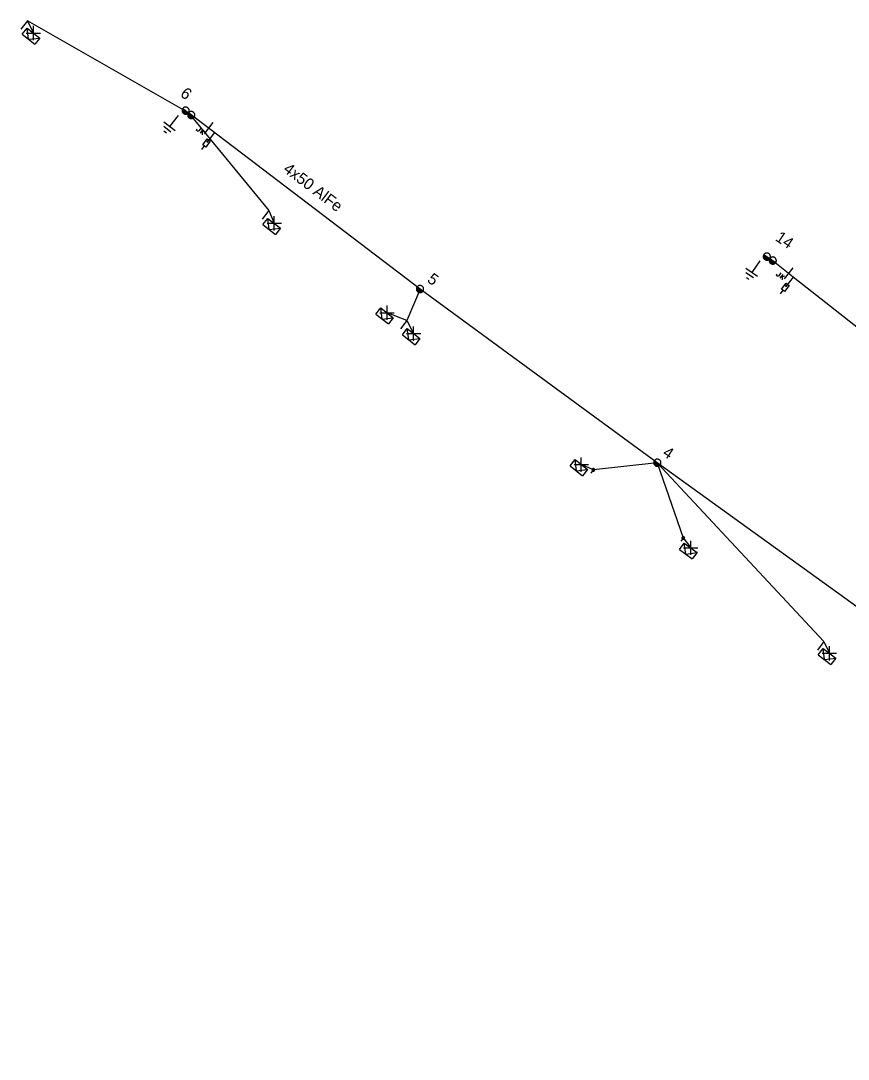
# Model space of a CAD drawing. Extents: x -544780 to -541582, y -1198995 to -1196551.
# Drawn here: x -543128.8 to -543056.3, y -1198154.6 to -1198063.6 of the extents above; entities that cross this region are included whole.
import ezdxf

# ---------------------------------------------------------------- set-up
doc = ezdxf.new("R2010")
doc.units = 0
for name, color, linetype in [('Vrstva 1', 7, 'Continuous'), ('Vrstva 13', 7, 'Continuous'), ('Vrstva 14', 7, 'Continuous'), ('Vrstva 15', 7, 'Continuous'), ('Vrstva 16', 7, 'Continuous'), ('Vrstva 18', 7, 'Continuous'), ('Vrstva 2', 7, 'Continuous'), ('Vrstva 31', 7, 'Continuous'), ('Vrstva 34', 7, 'Continuous'), ('Vrstva 54', 7, 'Continuous'), ('Vrstva 59', 7, 'Continuous'), ('Vrstva 8', 7, 'Continuous'), ('Vrstva 9', 7, 'Continuous')]:
    doc.layers.add(name, color=color, linetype=linetype)

# ---------------------------------------------------------------- blocks, each defined once
blk = doc.blocks.new('NN440')
at = {"layer": 'Vrstva 2'}
for points in [[(0.63, 0), (0.63, 0.06), (0.62, 0.13), (0.6, 0.19), (0.58, 0.25), (0.55, 0.31), (0.51, 0.37), (0.47, 0.42), (0.42, 0.46), (0.37, 0.51), (0.32, 0.54), (0.26, 0.57), (0.2, 0.59), (0.13, 0.61), (0.07, 0.62), (0, 0.63), (-0.06, 0.62), (-0.13, 0.61), (-0.19, 0.59), (-0.26, 0.57), (-0.31, 0.54), (-0.37, 0.51), (-0.42, 0.46), (-0.47, 0.42), (-0.51, 0.37), (-0.54, 0.31), (-0.57, 0.25), (-0.6, 0.19), (-0.62, 0.13), (-0.63, 0.06), (-0.63, 0), (-0.63, -0.07), (-0.62, -0.14), (-0.6, -0.2), (-0.57, -0.26), (-0.54, -0.32), (-0.51, -0.37), (-0.47, -0.43), (-0.42, -0.47), (-0.37, -0.51), (-0.31, -0.55), (-0.26, -0.58), (-0.19, -0.6), (-0.13, -0.62), (-0.06, -0.63), (0, -0.63), (0.07, -0.63), (0.13, -0.62), (0.2, -0.6), (0.26, -0.58), (0.32, -0.55), (0.37, -0.51), (0.42, -0.47), (0.47, -0.43), (0.51, -0.37), (0.55, -0.32), (0.58, -0.26), (0.6, -0.2), (0.62, -0.14), (0.63, -0.07), (0.63, 0)], [(-0.63, 0), (0.63, 0)], [(-0.6, -0.18), (0.57, -0.18)], [(-0.51, -0.32), (0.5, -0.32)], [(-0.37, -0.47), (0.35, -0.47)]]:
    blk.add_lwpolyline(points, dxfattribs=at)
blk = doc.blocks.new('NN450')
at = {"layer": 'Vrstva 2'}
for points in [[(0, 0), (0, 0.07), (-0.01, 0.13), (-0.03, 0.19), (-0.05, 0.25), (-0.08, 0.31), (-0.12, 0.37), (-0.16, 0.42), (-0.21, 0.46), (-0.26, 0.51), (-0.31, 0.54), (-0.37, 0.57), (-0.43, 0.59), (-0.5, 0.61), (-0.56, 0.62), (-0.63, 0.62), (-0.69, 0.62), (-0.75, 0.61), (-0.82, 0.59), (-0.88, 0.57), (-0.94, 0.54), (-0.99, 0.51), (-1.04, 0.46), (-1.09, 0.42), (-1.13, 0.37), (-1.17, 0.31), (-1.2, 0.25), (-1.22, 0.19), (-1.24, 0.13), (-1.25, 0.07), (-1.25, 0), (-1.25, -0.07), (-1.24, -0.13), (-1.22, -0.19), (-1.2, -0.25), (-1.17, -0.31), (-1.13, -0.37), (-1.09, -0.42), (-1.04, -0.46), (-0.99, -0.51), (-0.94, -0.54), (-0.88, -0.57), (-0.82, -0.59), (-0.75, -0.61), (-0.69, -0.62), (-0.62, -0.63), (-0.56, -0.62), (-0.5, -0.61), (-0.43, -0.59), (-0.37, -0.57), (-0.31, -0.54), (-0.26, -0.51), (-0.21, -0.46), (-0.16, -0.42), (-0.12, -0.37), (-0.08, -0.31), (-0.05, -0.25), (-0.03, -0.19), (-0.01, -0.13), (0, -0.07), (0, 0)], [(1.25, 0), (1.25, 0.07), (1.24, 0.13), (1.22, 0.19), (1.2, 0.25), (1.17, 0.31), (1.13, 0.37), (1.09, 0.42), (1.04, 0.46), (0.99, 0.51), (0.94, 0.54), (0.88, 0.57), (0.82, 0.59), (0.75, 0.61), (0.69, 0.62), (0.62, 0.62), (0.56, 0.62), (0.5, 0.61), (0.43, 0.59), (0.37, 0.57), (0.31, 0.54), (0.26, 0.51), (0.21, 0.46), (0.16, 0.42), (0.12, 0.37), (0.08, 0.31), (0.05, 0.25), (0.03, 0.19), (0.01, 0.13), (0, 0.07), (0, 0), (0, -0.07), (0.01, -0.13), (0.03, -0.19), (0.05, -0.25), (0.08, -0.31), (0.12, -0.37), (0.16, -0.42), (0.21, -0.46), (0.26, -0.51), (0.31, -0.54), (0.37, -0.57), (0.43, -0.59), (0.5, -0.61), (0.56, -0.62), (0.63, -0.63), (0.69, -0.62), (0.75, -0.61), (0.82, -0.59), (0.88, -0.57), (0.94, -0.54), (0.99, -0.51), (1.04, -0.46), (1.09, -0.42), (1.13, -0.37), (1.17, -0.31), (1.2, -0.25), (1.22, -0.19), (1.24, -0.13), (1.25, -0.07), (1.25, 0)], [(-1.25, 0), (1.25, 0)], [(-1.23, -0.16), (-0.02, -0.16)], [(-1.16, -0.32), (-0.09, -0.32)], [(-1.03, -0.47), (-0.22, -0.47)], [(0.02, -0.16), (1.23, -0.16)], [(0.09, -0.32), (1.16, -0.32)], [(0.22, -0.47), (1.03, -0.47)]]:
    blk.add_lwpolyline(points, dxfattribs=at)
blk = doc.blocks.new('NN840')
at = {"layer": 'Vrstva 15'}
for points in [[(0.003, 0.619), (0.003, -0.631)], [(-0.745, -0.71), (-0.745, -0.66)], [(-0.73, -0.764), (-0.745, -0.71)], [(-0.657, -0.798), (-0.73, -0.764)], [(-0.627, -0.798), (-0.657, -0.798)], [(-0.558, -0.764), (-0.627, -0.798)], [(-0.538, -0.71), (-0.558, -0.764)], [(-0.538, -0.385), (-0.538, -0.71)], [(-0.332, -0.385), (-0.332, -0.798)], [(-0.332, -0.641), (-0.125, -0.385)], [(-0.263, -0.557), (-0.091, -0.798)]]:
    blk.add_lwpolyline(points, dxfattribs=at)
blk = doc.blocks.new('NN800')
at = {"layer": 'Vrstva 1'}
for points in [[(-0.442, 0.442), (0.442, -0.442)], [(-0.442, -0.442), (0.442, 0.442)]]:
    blk.add_lwpolyline(points, dxfattribs=at)
blk = doc.blocks.new('NN820')
at = {"layer": 'Vrstva 13'}
for points in [[(-0.003, 0.004), (-0.003, -1.049)], [(-0.165, -0.813), (0.165, -0.813)], [(-0.165, -1.473), (-0.165, -0.813)], [(0.165, -0.813), (0.165, -1.473)], [(0.165, -1.473), (-0.165, -1.473)], [(-0.003, -1.049), (-0.062, -0.926)], [(-0.003, -1.049), (0.057, -0.926)], [(-0.003, -1.473), (-0.003, -1.871)]]:
    blk.add_lwpolyline(points, dxfattribs=at)
blk = doc.blocks.new('NN630')
at = {"layer": 'Vrstva 9'}
for points in [[(-0.003, -0.7), (-0.703, 0)], [(-0.703, -0.7), (-0.703, 0), (0.697, 0), (0.697, -0.7)], [(-0.703, -0.7), (0.697, -0.7)], [(-0.003, -0.7), (0.697, 0)]]:
    blk.add_lwpolyline(points, dxfattribs=at)
blk = doc.blocks.new('NN810')
at = {"layer": 'Vrstva 14'}
for points in [[(0.004, -0.64), (0.004, -1.89)], [(0.629, -1.89), (-0.621, -1.89)], [(0.388, -2.2), (-0.399, -2.2)], [(0.004, -2.515), (-0.124, -2.515)], [(0.137, -2.515), (0.004, -2.515)]]:
    blk.add_lwpolyline(points, dxfattribs=at)
blk = doc.blocks.new('NN500')
at = {"layer": 'Vrstva 2'}
for points in [[(0, -0.24), (0.02, -0.23), (0.05, -0.23), (0.07, -0.22), (0.09, -0.22), (0.12, -0.2), (0.14, -0.19), (0.16, -0.18), (0.17, -0.16), (0.19, -0.14), (0.2, -0.12), (0.21, -0.1), (0.22, -0.07), (0.23, -0.05), (0.23, -0.02), (0.23, 0), (0.23, 0.02), (0.23, 0.05), (0.22, 0.07), (0.21, 0.1), (0.2, 0.12), (0.19, 0.14), (0.17, 0.16), (0.16, 0.17), (0.14, 0.19), (0.12, 0.2), (0.09, 0.21), (0.07, 0.22), (0.05, 0.23), (0.02, 0.23), (0, 0.23), (-0.03, 0.23), (-0.05, 0.23), (-0.07, 0.22), (-0.1, 0.21), (-0.12, 0.2), (-0.14, 0.19), (-0.16, 0.17), (-0.18, 0.16), (-0.19, 0.14), (-0.2, 0.12), (-0.22, 0.1), (-0.22, 0.07), (-0.23, 0.05), (-0.23, 0.02), (-0.24, 0), (-0.23, -0.02), (-0.23, -0.05), (-0.22, -0.07), (-0.22, -0.1), (-0.2, -0.12), (-0.19, -0.14), (-0.18, -0.16), (-0.16, -0.18), (-0.14, -0.19), (-0.12, -0.2), (-0.1, -0.22), (-0.07, -0.22), (-0.05, -0.23), (-0.03, -0.23), (0, -0.24)], [(0, -0.24), (0.02, -0.23), (0.05, -0.23), (0.07, -0.22), (0.09, -0.22), (0.12, -0.2), (0.14, -0.19), (0.16, -0.18), (0.17, -0.16), (0.19, -0.14), (0.2, -0.12), (0.21, -0.1), (0.22, -0.07), (0.23, -0.05), (0.23, -0.02), (0.23, 0), (0.23, 0.02), (0.23, 0.05), (0.22, 0.07), (0.21, 0.1), (0.2, 0.12), (0.19, 0.14), (0.17, 0.16), (0.16, 0.17), (0.14, 0.19), (0.12, 0.2), (0.09, 0.21), (0.07, 0.22), (0.05, 0.23), (0.02, 0.23), (0, 0.23), (-0.03, 0.23), (-0.05, 0.23), (-0.07, 0.22), (-0.1, 0.21), (-0.12, 0.2), (-0.14, 0.19), (-0.16, 0.17), (-0.18, 0.16), (-0.19, 0.14), (-0.2, 0.12), (-0.22, 0.1), (-0.22, 0.07), (-0.23, 0.05), (-0.23, 0.02), (-0.24, 0), (-0.23, -0.02), (-0.23, -0.05), (-0.22, -0.07), (-0.22, -0.1), (-0.2, -0.12), (-0.19, -0.14), (-0.18, -0.16), (-0.16, -0.18), (-0.14, -0.19), (-0.12, -0.2), (-0.1, -0.22), (-0.07, -0.22), (-0.05, -0.23), (-0.03, -0.23), (0, -0.24)], [(0, -0.21), (0.02, -0.2), (0.04, -0.2), (0.06, -0.2), (0.08, -0.19), (0.1, -0.18), (0.12, -0.17), (0.14, -0.15), (0.15, -0.14), (0.16, -0.12), (0.18, -0.1), (0.19, -0.08), (0.19, -0.06), (0.2, -0.04), (0.2, -0.02), (0.2, 0), (0.2, 0.02), (0.2, 0.04), (0.19, 0.06), (0.19, 0.08), (0.18, 0.1), (0.16, 0.12), (0.15, 0.14), (0.14, 0.15), (0.12, 0.17), (0.1, 0.18), (0.08, 0.19), (0.06, 0.19), (0.04, 0.2), (0.02, 0.2), (0, 0.2), (-0.02, 0.2), (-0.04, 0.2), (-0.06, 0.19), (-0.08, 0.19), (-0.1, 0.18), (-0.12, 0.17), (-0.14, 0.15), (-0.15, 0.14), (-0.17, 0.12), (-0.18, 0.1), (-0.19, 0.08), (-0.2, 0.06), (-0.2, 0.04), (-0.21, 0.02), (-0.21, 0), (-0.21, -0.02), (-0.2, -0.04), (-0.2, -0.06), (-0.19, -0.08), (-0.18, -0.1), (-0.17, -0.12), (-0.15, -0.14), (-0.14, -0.15), (-0.12, -0.17), (-0.1, -0.18), (-0.08, -0.19), (-0.06, -0.2), (-0.04, -0.2), (-0.02, -0.2), (0, -0.21)], [(0, -0.18), (0.02, -0.18), (0.04, -0.17), (0.05, -0.17), (0.07, -0.16), (0.09, -0.15), (0.1, -0.14), (0.12, -0.13), (0.13, -0.12), (0.14, -0.1), (0.15, -0.09), (0.16, -0.07), (0.17, -0.05), (0.17, -0.04), (0.17, -0.02), (0.17, 0), (0.17, 0.02), (0.17, 0.04), (0.17, 0.05), (0.16, 0.07), (0.15, 0.09), (0.14, 0.1), (0.13, 0.12), (0.12, 0.13), (0.1, 0.14), (0.09, 0.15), (0.07, 0.16), (0.05, 0.17), (0.04, 0.17), (0.02, 0.17), (0, 0.18), (-0.02, 0.17), (-0.04, 0.17), (-0.06, 0.17), (-0.07, 0.16), (-0.09, 0.15), (-0.1, 0.14), (-0.12, 0.13), (-0.13, 0.12), (-0.14, 0.1), (-0.15, 0.09), (-0.16, 0.07), (-0.17, 0.05), (-0.17, 0.04), (-0.18, 0.02), (-0.18, 0), (-0.18, -0.02), (-0.17, -0.04), (-0.17, -0.05), (-0.16, -0.07), (-0.15, -0.09), (-0.14, -0.1), (-0.13, -0.12), (-0.12, -0.13), (-0.1, -0.14), (-0.09, -0.15), (-0.07, -0.16), (-0.06, -0.17), (-0.04, -0.17), (-0.02, -0.18), (0, -0.18)], [(0, -0.15), (0.01, -0.15), (0.03, -0.14), (0.04, -0.14), (0.06, -0.13), (0.07, -0.13), (0.08, -0.12), (0.1, -0.11), (0.11, -0.1), (0.12, -0.09), (0.13, -0.07), (0.13, -0.06), (0.14, -0.05), (0.14, -0.03), (0.14, -0.02), (0.14, 0), (0.14, 0.01), (0.14, 0.03), (0.14, 0.04), (0.13, 0.06), (0.13, 0.07), (0.12, 0.09), (0.11, 0.1), (0.1, 0.11), (0.08, 0.12), (0.07, 0.13), (0.06, 0.13), (0.04, 0.14), (0.03, 0.14), (0.01, 0.14), (0, 0.15), (-0.02, 0.14), (-0.03, 0.14), (-0.05, 0.14), (-0.06, 0.13), (-0.07, 0.13), (-0.09, 0.12), (-0.1, 0.11), (-0.11, 0.1), (-0.12, 0.09), (-0.13, 0.07), (-0.13, 0.06), (-0.14, 0.04), (-0.14, 0.03), (-0.15, 0.01), (-0.15, 0), (-0.15, -0.02), (-0.14, -0.03), (-0.14, -0.05), (-0.13, -0.06), (-0.13, -0.07), (-0.12, -0.09), (-0.11, -0.1), (-0.1, -0.11), (-0.09, -0.12), (-0.07, -0.13), (-0.06, -0.13), (-0.05, -0.14), (-0.03, -0.14), (-0.02, -0.15), (0, -0.15)], [(0, -0.12), (0.01, -0.12), (0.02, -0.11), (0.03, -0.11), (0.05, -0.11), (0.06, -0.1), (0.07, -0.09), (0.08, -0.09), (0.09, -0.08), (0.09, -0.07), (0.1, -0.06), (0.11, -0.05), (0.11, -0.04), (0.11, -0.02), (0.11, -0.01), (0.12, 0), (0.11, 0.01), (0.11, 0.02), (0.11, 0.04), (0.11, 0.05), (0.1, 0.06), (0.09, 0.07), (0.09, 0.08), (0.08, 0.09), (0.07, 0.09), (0.06, 0.1), (0.05, 0.11), (0.03, 0.11), (0.02, 0.11), (0.01, 0.12), (0, 0.12), (-0.01, 0.12), (-0.03, 0.11), (-0.04, 0.11), (-0.05, 0.11), (-0.06, 0.1), (-0.07, 0.09), (-0.08, 0.09), (-0.09, 0.08), (-0.1, 0.07), (-0.1, 0.06), (-0.11, 0.05), (-0.11, 0.04), (-0.12, 0.02), (-0.12, 0.01), (-0.12, 0), (-0.12, -0.01), (-0.12, -0.02), (-0.11, -0.04), (-0.11, -0.05), (-0.1, -0.06), (-0.1, -0.07), (-0.09, -0.08), (-0.08, -0.09), (-0.07, -0.09), (-0.06, -0.1), (-0.05, -0.11), (-0.04, -0.11), (-0.03, -0.11), (-0.01, -0.12), (0, -0.12)], [(0, -0.09), (0.01, -0.09), (0.02, -0.09), (0.03, -0.08), (0.03, -0.08), (0.04, -0.08), (0.05, -0.07), (0.06, -0.07), (0.06, -0.06), (0.07, -0.05), (0.07, -0.04), (0.08, -0.04), (0.08, -0.03), (0.08, -0.02), (0.09, -0.01), (0.09, 0), (0.09, 0.01), (0.08, 0.02), (0.08, 0.03), (0.08, 0.03), (0.07, 0.04), (0.07, 0.05), (0.06, 0.06), (0.06, 0.06), (0.05, 0.07), (0.04, 0.07), (0.03, 0.08), (0.03, 0.08), (0.02, 0.08), (0.01, 0.09), (0, 0.09), (-0.01, 0.09), (-0.02, 0.08), (-0.03, 0.08), (-0.04, 0.08), (-0.04, 0.07), (-0.05, 0.07), (-0.06, 0.06), (-0.07, 0.06), (-0.07, 0.05), (-0.08, 0.04), (-0.08, 0.03), (-0.08, 0.03), (-0.09, 0.02), (-0.09, 0.01), (-0.09, 0), (-0.09, -0.01), (-0.09, -0.02), (-0.08, -0.03), (-0.08, -0.04), (-0.08, -0.04), (-0.07, -0.05), (-0.07, -0.06), (-0.06, -0.07), (-0.05, -0.07), (-0.04, -0.08), (-0.04, -0.08), (-0.03, -0.08), (-0.02, -0.09), (-0.01, -0.09), (0, -0.09)], [(0, -0.06), (0, -0.06), (0.01, -0.06), (0.02, -0.05), (0.02, -0.05), (0.03, -0.05), (0.03, -0.05), (0.04, -0.04), (0.04, -0.04), (0.05, -0.03), (0.05, -0.03), (0.05, -0.02), (0.05, -0.02), (0.05, -0.01), (0.06, -0.01), (0.06, 0), (0.06, 0.01), (0.05, 0.01), (0.05, 0.02), (0.05, 0.02), (0.05, 0.03), (0.05, 0.03), (0.04, 0.04), (0.04, 0.04), (0.03, 0.05), (0.03, 0.05), (0.02, 0.05), (0.02, 0.05), (0.01, 0.06), (0, 0.06), (0, 0.06), (-0.01, 0.06), (-0.01, 0.06), (-0.02, 0.05), (-0.02, 0.05), (-0.03, 0.05), (-0.03, 0.05), (-0.04, 0.04), (-0.04, 0.04), (-0.05, 0.03), (-0.05, 0.03), (-0.05, 0.02), (-0.06, 0.02), (-0.06, 0.01), (-0.06, 0.01), (-0.06, 0), (-0.06, -0.01), (-0.06, -0.01), (-0.06, -0.02), (-0.05, -0.02), (-0.05, -0.03), (-0.05, -0.03), (-0.04, -0.04), (-0.04, -0.04), (-0.03, -0.05), (-0.03, -0.05), (-0.02, -0.05), (-0.02, -0.05), (-0.01, -0.06), (-0.01, -0.06), (0, -0.06)], [(0, -0.03), (0, -0.03), (0, -0.03), (0.01, -0.03), (0.01, -0.03), (0.01, -0.02), (0.02, -0.02), (0.02, -0.02), (0.02, -0.02), (0.02, -0.02), (0.02, -0.01), (0.02, -0.01), (0.03, -0.01), (0.03, -0.01), (0.03, 0), (0.03, 0), (0.03, 0), (0.03, 0.01), (0.03, 0.01), (0.02, 0.01), (0.02, 0.01), (0.02, 0.02), (0.02, 0.02), (0.02, 0.02), (0.02, 0.02), (0.01, 0.02), (0.01, 0.02), (0.01, 0.03), (0, 0.03), (0, 0.03), (0, 0.03), (0, 0.03), (-0.01, 0.03), (-0.01, 0.03), (-0.01, 0.02), (-0.02, 0.02), (-0.02, 0.02), (-0.02, 0.02), (-0.02, 0.02), (-0.02, 0.02), (-0.03, 0.01), (-0.03, 0.01), (-0.03, 0.01), (-0.03, 0.01), (-0.03, 0), (-0.03, 0), (-0.03, 0), (-0.03, -0.01), (-0.03, -0.01), (-0.03, -0.01), (-0.03, -0.01), (-0.02, -0.02), (-0.02, -0.02), (-0.02, -0.02), (-0.02, -0.02), (-0.02, -0.02), (-0.01, -0.03), (-0.01, -0.03), (-0.01, -0.03), (0, -0.03), (0, -0.03)], [(0.23, 0), (0.7, 0)]]:
    blk.add_lwpolyline(points, dxfattribs=at)
blk = doc.blocks.new('NN510')
at = {"layer": 'Vrstva 2'}
blk.add_lwpolyline([(0.001, 0.002), (0.001, 0.939)], dxfattribs=at)

msp = doc.modelspace()

# ---------------------------------------------------------------- linework, layer by layer
at = {"layer": 'Vrstva 1'}
for points in [[(-542976.81, -1198179.454), (-542992.97, -1198160.1), (-543021.7, -1198139.37), (-543048.73, -1198119.86), (-543073.03, -1198102.33), (-543093.82, -1198087.11), (-543114.12, -1198071.67)], [(-542959.64, -1198153.06), (-542988.53, -1198140.01), (-543015.01, -1198121.6), (-543020.571, -1198116.642), (-543029.441, -1198110.122), (-543042.654, -1198099.919), (-543054.178, -1198091.528), (-543061.112, -1198086.062), (-543063.17, -1198084.44)]]:
    msp.add_lwpolyline(points, dxfattribs=at)
at = {"layer": 'Vrstva 54'}
for points in [[(-543114.12, -1198071.67), (-543128.229, -1198063.602), (-543127.701, -1198064.679)], [(-543114.12, -1198071.67), (-543107.064, -1198080.239), (-543106.602, -1198081.352)], [(-543093.82, -1198087.11), (-543094.97, -1198089.872)], [(-543073.03, -1198102.33), (-543078.636, -1198102.957), (-543079.69, -1198102.49)], [(-543073.03, -1198102.33), (-543070.759, -1198108.928), (-543070.101, -1198109.789)]]:
    msp.add_lwpolyline(points, dxfattribs=at)
at = {"layer": 'Vrstva 59'}
for points in [[(-543094.97, -1198089.872), (-543096.71, -1198089.193)], [(-543094.97, -1198089.872), (-543094.383, -1198091.015)]]:
    msp.add_lwpolyline(points, dxfattribs=at)
at = {"layer": 'Vrstva 8'}
msp.add_lwpolyline([(-543073.03, -1198102.33), (-543058.426, -1198118.003), (-543057.948, -1198119.024)], dxfattribs=at)

# ---------------------------------------------------------------- block references
at = {"layer": 'Vrstva 13'}
for p, rotation in [((-543128.228, -1198063.602), 141.53027232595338), ((-543107.064, -1198080.239), 141.76359444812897), ((-543094.97, -1198089.872), 142.15485281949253), ((-543058.425, -1198118.003), 142.93240276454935)]:
    msp.add_blockref('NN510', p, dxfattribs=dict(at, rotation=rotation))
for name, p, xscale, yscale, rotation in [('NN450', (-543114.12, -1198071.67), 0.5, 0.5, -38.02380267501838), ('NN450', (-543063.17, -1198084.44), 0.5000000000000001, 0.5000000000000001, -34.0567027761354), ('NN440', (-543093.821, -1198087.111), 0.5, 0.5, -36.23637216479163), ('NN440', (-543073.03, -1198102.329), 0.5, 0.5, -33.48734167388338), ('NN500', (-543078.636, -1198102.957), 0.5, 0.5, -128.10200005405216), ('NN500', (-543070.759, -1198108.928), 0.5, 0.5, -126.72499997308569)]:
    msp.add_blockref(name, p, dxfattribs=dict(at, xscale=xscale, yscale=yscale, rotation=rotation))
at = {"layer": 'Vrstva 15'}
for p, rotation in [((-543114.615, -1198071.384), -38.023802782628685), ((-543063.7, -1198084.102), -34.0567027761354)]:
    msp.add_blockref('NN810', p, dxfattribs=dict(at, rotation=rotation))
at = {"layer": 'Vrstva 16'}
for p, rotation in [((-543111.848, -1198073.398), -37.25629718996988), ((-543061.112, -1198086.062), -38.24716664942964)]:
    msp.add_blockref('NN820', p, dxfattribs=dict(at, rotation=rotation))
at = {"layer": 'Vrstva 18'}
for p, rotation in [((-543112.356, -1198073.012), -37.25629729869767), ((-543061.531, -1198085.732), -38.24716664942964)]:
    msp.add_blockref('NN840', p, dxfattribs=dict(at, rotation=rotation))
at = {"layer": 'Vrstva 31'}
for p, rotation in [((-543127.701, -1198064.679), -38.46972778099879), ((-543106.602, -1198081.352), -38.236405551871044), ((-543096.71, -1198089.193), -38.48259446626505), ((-543094.383, -1198091.015), -37.845147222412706), ((-543079.69, -1198102.49), -38.1023610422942), ((-543070.101, -1198109.789), -36.72507786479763), ((-543057.948, -1198119.024), -37.067597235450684)]:
    msp.add_blockref('NN630', p, dxfattribs=dict(at, rotation=rotation))
at = {"layer": 'Vrstva 34'}
for p, rotation in [((-543127.701, -1198064.679), 45), ((-543106.602, -1198081.352), 45.000000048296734), ((-543096.71, -1198089.193), 45), ((-543094.383, -1198091.015), 45), ((-543079.69, -1198102.49), 44.99999995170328), ((-543070.101, -1198109.789), 45), ((-543057.948, -1198119.024), 45)]:
    msp.add_blockref('NN800', p, dxfattribs=dict(at, rotation=rotation))

# ---------------------------------------------------------------- texts
at = {"layer": 'Vrstva 14'}
for s, rotation, p in [('6', 321.976, (-543114.91, -1198070.136)), ('14', 325.943, (-543062.76, -1198082.805)), ('5', 323.764, (-543093.273, -1198086.429)), ('4', 326.513, (-543072.644, -1198101.663))]:
    msp.add_text(s, height=1, rotation=rotation, dxfattribs=at).set_placement(p)
at = {"layer": 'Vrstva 2'}
msp.add_text('4x50 AlFe', height=1, rotation=322.744, dxfattribs=at).set_placement((-543105.885, -1198076.757))

doc.saveas('drawing.dxf')
